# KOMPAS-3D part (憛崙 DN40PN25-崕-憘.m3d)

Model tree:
1. Объединить компоненты:1  (labels: СЕНС DN40PN25-НО)
2. Эскиз:1
3. Операция выдавливания:1
     Расстояние 1 = 14
4. Фаска:1
     Угол = 45; Длина 1 = 2; Длина 2 = 2

Referenced files in D:\Савин\!СЕНСОР\3D для заказчика\!Новый перечень\СЕНС\2. СЕНС-НО\DN40\: СЕНС DN40PN25-НО.a3d
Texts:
  СЕНС DN40PN25-НО-СВ
  ООО НПП Сенсор
  СЕНС DN40PN25-НО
